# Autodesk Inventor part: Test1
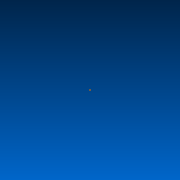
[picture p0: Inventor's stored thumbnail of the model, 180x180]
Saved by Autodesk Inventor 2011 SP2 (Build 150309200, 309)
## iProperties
Created: 2012-03
Part Number: Test1
Document SubType Name: Modeling
Designer: BH
Density: 1 g/cm^3
Author: BH
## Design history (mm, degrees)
sketch "Skizze1"
  geometry: L1 (0, 0)-(100, 0); L2 (100, 0)-(100, -40); L3 (100, -40)-(0, -40); L4 (0, -40)-(0, 0)
  constraints: 8 end point, 2 parallel, 1 horizontal, 1 perpendicular
  dimensions: "d0" = 100 distance of L2.end L3.end; "d1" = 40 distance of L1.end L2.end
extrude "Extrusion1" new body sketch "Skizze1" distance "d2" = 10; taper "d3" = 0 deg
sketch "Skizze2"
  geometry: L1 (50, -3.603)-(34.16, -3.603); L2 (34.16, -3.603)-(34.16, -7.505); L3 (34.16, -7.505)-(50, -7.505); L4 (50, -7.505)-(50, -3.603)
  constraints: 8 end point, 2 parallel, 1 horizontal, 1 perpendicular
extrude "Extrusion2" cut sketch "Skizze2" distance "d4" = 10; taper "d5" = 0 deg
node "Volumenkörper1"
